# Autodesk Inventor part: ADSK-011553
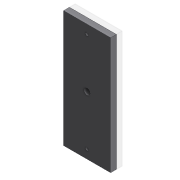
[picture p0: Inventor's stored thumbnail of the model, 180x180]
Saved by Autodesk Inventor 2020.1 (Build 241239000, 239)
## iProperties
Created: 2000-02
Part Number: ADSK-011553
Material: Pearson HRS
Document SubType Name: Modeling
Designer: glanglot
Density: 7.83 g/cm^3
Appearance: Métal - Acier
Mass: 2515.04 g
Surface Area: 613.414 cm^2
Volume: 321.205 cm^3
Control State: 0
Checked Out: False
Master: False
Shininess: 0.0
Length Units: 11269
Angle Units: 11279
Time Units: 11290
Mass Units: 11283
Length Display Precision: 3
Angle Display Precision: 2
Compacted: True
Cutlength: 10
Material Desc: FLAT,HRS,0.500X04.000
Material_Number: A084316
Dimensions: 102x254x12,5 mm
Mass: 2,515 kg
Density: 0.0
Volumn: 0.0
Area: 0.0
PropertySet Name: Model Information
Author: glanglot
Revision Number: -
Title: ADSK-011553
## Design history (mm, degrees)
node "Solide1"
  node "Extrusion1" dims "d5" = 12.5, "d6" = 0
  node "Hole1" dims "d7" = 6.6, "d8" = 9.525, "d9" = 6.35, "d10" = 60 deg, "d11" = 19.05, "d12" = 118 deg, "d19" = 6
  node "Hole2" dims "d13" = 13.5, "d14" = 9.525, "d15" = 6.35, "d16" = 60 deg, "d17" = 41.3, "d18" = 118 deg, "d20" = 32
sketch "Sketch1"
  geometry: L1 (0, 0)-(-102, 0); L2 (-102, 0)-(-102, -254); L3 (-102, -254)-(0, -254); L4 (0, -254)-(0, 0); L5 (-51, 0)-(-51, -254); L6 (-102, -127)-(0, -127); 3 further points
  constraints: 12 end point, 5 midpoint, 2 parallel, 2 point on line, 1 horizontal, 1 perpendicular
  dimensions: "d0" = 254 distance between parallel lines of L3 L1; "d1" = 102 distance between parallel lines of L4 L2; "d2" = 108 distance from line of L6 point (-51, -19); "d3" = 108 distance from line of point (-51, -235) L6 (= d2)
node "Corps solides"
node "Corps surfaciques"
